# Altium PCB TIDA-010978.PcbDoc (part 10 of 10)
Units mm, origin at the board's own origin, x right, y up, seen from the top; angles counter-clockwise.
Board outline 243.95 x 94.85 mm, 4 copper layers (Top Layer, Mid Layer 1, Mid Layer 2, Bottom Layer), stack 1.623 mm thick; 865 components, 374 nets, 2308 pads, 2132 vias.
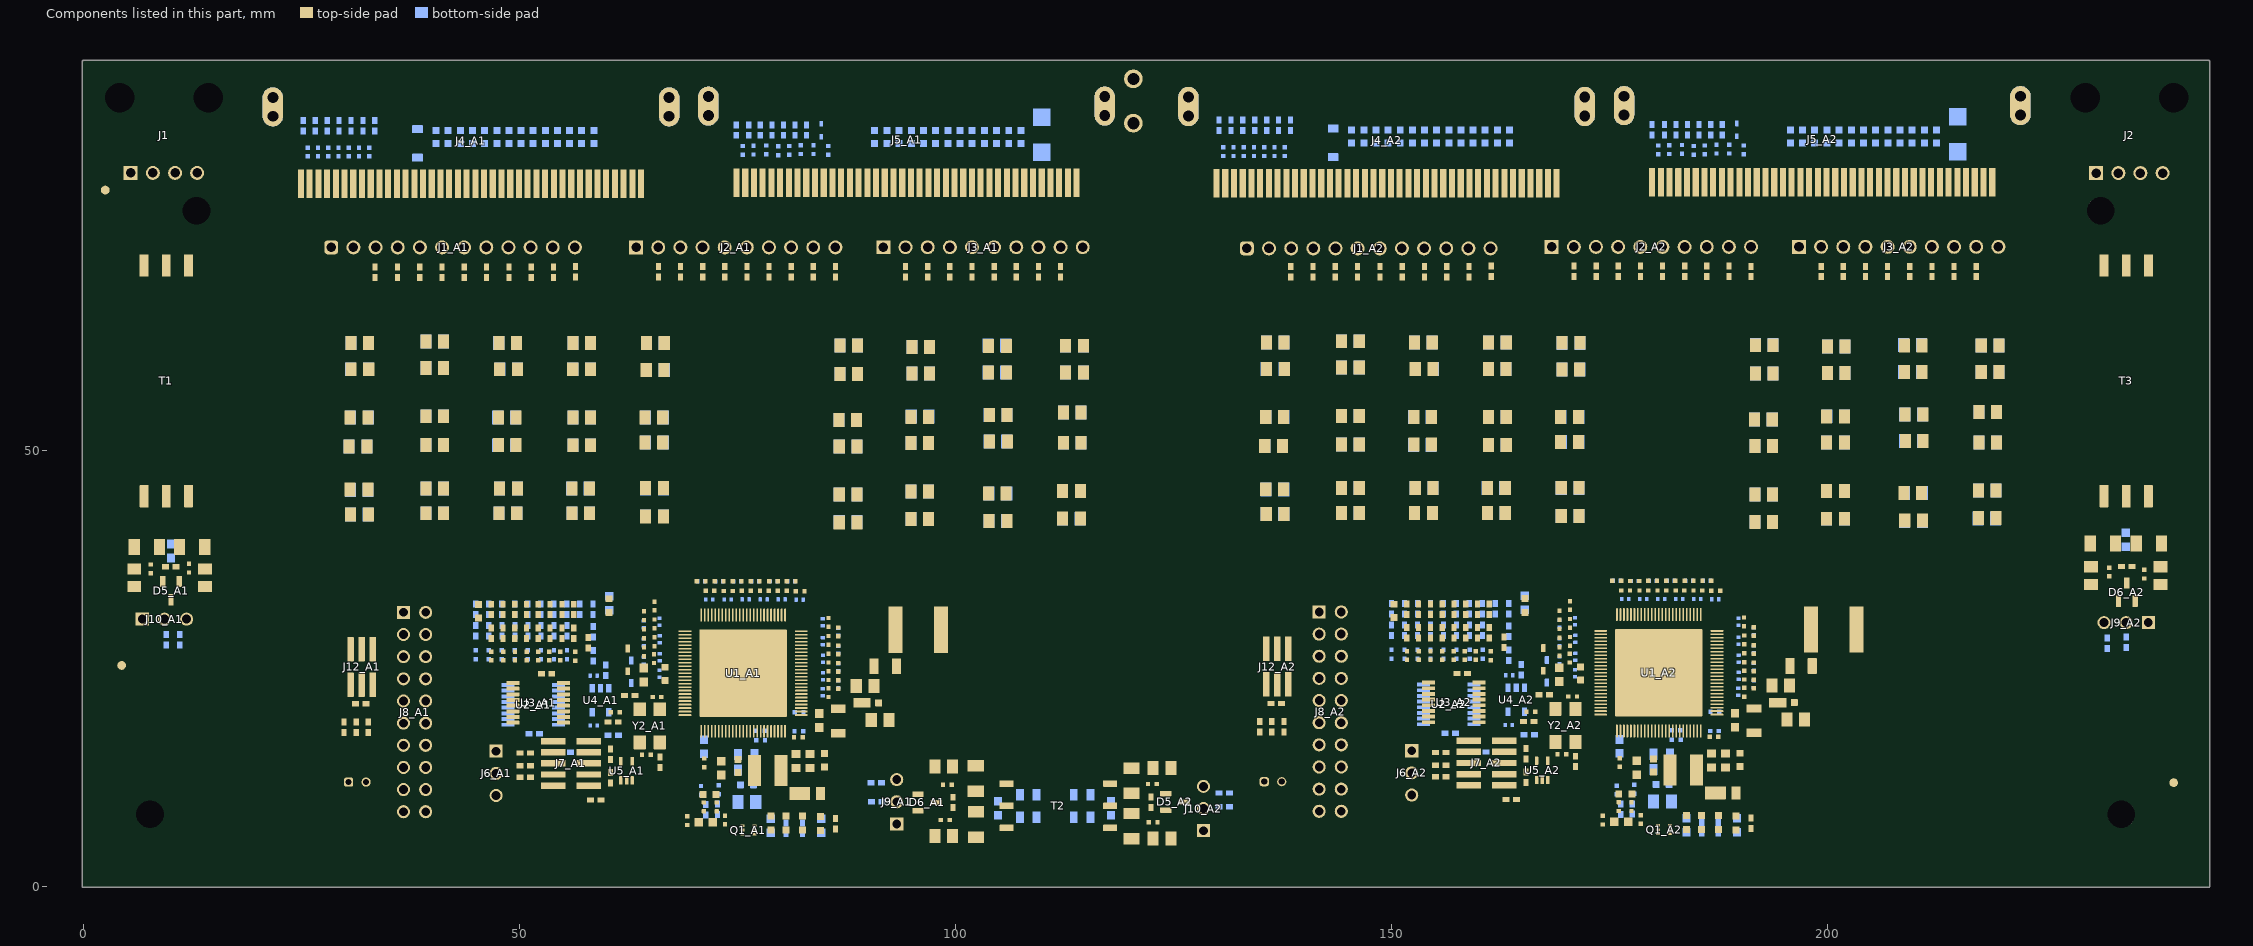
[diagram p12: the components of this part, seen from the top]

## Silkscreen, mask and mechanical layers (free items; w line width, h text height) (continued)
M9 Title Sheet:
  drawing of 56 lines, arcs and shapes, not listed
  text "1" at 26.882,339.887 h1.78
  text "2" at 111.354,339.887 h1.78
  text "3" at 195.936,339.887 h1.78
  text "4" at 280.645,339.887 h1.78
  text "5" at 365.1,339.887 h1.78
  text "6" at 449.809,339.887 h1.78
  text "A" at -11.76,294.726 h1.78
  text "A" at 488.62,294.726 h1.78
  text "B" at -11.76,199.476 h1.78
  text "B" at 488.62,199.476 h1.78
  text "C" at -11.76,104.226 h1.78
  text "C" at 488.62,104.226 h1.78
  text "D" at -11.76,8.976 h1.78
  text "D" at 488.62,8.976 h1.78
  text "PROJECT TITLE:" at 410.032,6.817 h1.14
  text ".PRJ_Title" at 411.302,3.431 h1.78
  text "DESIGNED FOR:" at 410.032,-0.828 h1.14
  text ".PRJ_Customer" at 411.302,-4.384 h1.78
  text "FILE NAME:" at 410.032,-8.448 h1.14
  text ".PCB_File_Name_No_Path" at 411.302,-11.496 h1.78
  text "Texas Instruments (TI) and/or its licensors do not warrant the accuracy or completeness of this specification" at 283.807,-15.607 h1.14
  text "ENGINEER:" at 410.032,-15.814 h1.14
  text "LAYOUT BY:" at 448.259,-15.814 h1.14
  text "or any information contained therein. TI and/or its licensors do not warrant that this design will meet" at 282.664,-18.469 h1.14
  text ".PRJ_Engineer" at 411.302,-19.751 h1.78
  text ".PCB_Layout" at 449.542,-19.751 h1.78
  text "the specifications, will be suitable for your application or fit for any particular purpose, or will operate in" at 282.664,-21.33 h1.14
  text ".Layer_Name" at 14.656,-21.806 h1.52
  text "ALTIUM DESIGNER VERSION:" at 448.259,-23.688 h1.14
  text "an implementation. TI and/or its licensors do not warrant that the design is production worthy. You should" at 282.664,-24.192 h1.14
  text "completely validate and test your design implementation to confirm the system functionality for your application." at 283.807,-27.054 h1.14
  text ".print_Scale" at 411.302,-27.075 h1.78
  text ".Application_BuildNumber" at 449.542,-27.075 h1.78
  text "1" at 26.882,-33.493 h1.78
  text "2" at 111.354,-33.493 h1.78
  text "3" at 195.936,-33.493 h1.78
  text "4" at 280.645,-33.493 h1.78
  text "5" at 365.1,-33.493 h1.78
  text "6" at 449.809,-33.493 h1.78
M10 Fab Notes:
  drawing of 189 lines, arcs and shapes, not listed
  text "DESIGN INFORMATION" at 436.322,161.675 h1.52
  text "MIN. TRACK WIDTH:" at 419.95,158.319 h1.52
  text "8" at 447.794,158.32 h1.52
  text "MIL" at 451.725,158.319 h1.52
  text "MIN. CLEARANCE:" at 419.95,155.167 h1.52
  text "MIL" at 451.725,155.167 h1.52
  text "7.874" at 443.475,155.05 h1.52
  text "MIN. VIA PAD SIZE:" at 419.95,152.014 h1.52
  text "24" at 447.033,152.014 h1.52
  text "MIL" at 451.725,152.014 h1.52
  text "0.05mm (2MIL)" at 437.603,148.714 h1.52
  text "MINIMUM ANNULAR RING" at 411.587,148.506 h1.52
  text "EXTERNAL" at 455.586,148.506 h1.52
  text "PER" at 416.667,145.708 h1.52
  text "IPC-D-275 CLASS 2 LEVEL C" at 422.255,145.708 h1.52
  text "MIL, HOLES" at 460.056,143.156 h1.52
  text "+/-" at 450.088,142.938 h1.52
  text "+/-" at 471.78,142.938 h1.52
  text "REGISTRATION TOLERANCES:" at 411.587,142.911 h1.52
  text "METAL" at 442.062,142.911 h1.52
  text "5" at 456.697,142.911 h1.52
  text "3" at 477.855,142.911 h1.52
  text "MIL" at 480.808,142.911 h1.52
  text "HOLE SIZE TOLERANCE (UNLESS OTHERWISE SPECIFIED):" at 411.587,140.414 h1.52
  text "+/-" at 471.78,140.341 h1.52
  text "3" at 477.855,140.314 h1.52
  text "MIL" at 480.808,140.314 h1.52
  text "MATERIAL:" at 409.688,136.818 h1.52
  text "FR-4 High Tg" at 434.744,133.553 h1.52
  text "X" at 431.075,133.35 h1.52
  text "FR-4" at 420.382,133.235 h1.52
  text "OTHER" at 458.177,133.235 h1.52
  text "62 MIL (1.6mm) +/-10%" at 428.512,129.602 h1.52
  text "X" at 425.462,129.54 h1.52
  text "THICKNESS:" at 411.587,129.394 h1.52
  text "OTHER" at 461.149,129.394 h1.52
  text "TOLERANCE:" at 411.587,125.88 h1.52
  text "X" at 433.133,125.88 h1.52
  text "ANSI IPC-6012 TYPE 3 CLASS 2" at 437.654,125.88 h1.52
  text "OTHER +/-" at 437.654,122.218 h1.52
  text "BOW & TWIST:" at 411.587,118.53 h1.52
  text "X" at 433.133,118.53 h1.52
  text "ANSI IPC-6012 TYPE 3 CLASS 2" at 437.654,118.53 h1.52
  text "OTHER +/-" at 437.654,114.804 h1.52
  text "DRILLING:" at 409.688,111.486 h1.52
  text "NC_DRILL FILES" at 454.418,108.815 h1.52
  text "REFERENCE:" at 411.587,108.715 h1.52
  text "X" at 428.281,108.712 h1.52
  text "AS SHOWN" at 432.802,108.715 h1.52
  text "X" at 451.167,108.715 h1.52
  text "OTHER" at 461.987,105.101 h1.52
  text "PTH COPPER THICKNESS:" at 411.579,105.012 h1.52
  text "X" at 440.516,105.012 h1.52
  text "20-30 um" at 443.767,105.012 h1.52
  text "BOARD FINISH:" at 409.688,101.263 h1.52
  text "SILKSCREEN:" at 413.631,98.466 h1.52
  text "X" at 437.959,98.466 h1.52
  text "TOP" at 440.93,98.466 h1.52
  text "X" at 450.913,98.466 h1.52
  text "BOTTOM" at 453.91,98.466 h1.52
  text "SILKSCREEN COLOR:" at 413.631,94.524 h1.52
  text "X" at 437.933,94.524 h1.52
  text "WHITE" at 440.93,94.524 h1.52
  text "OTHER" at 453.91,94.524 h1.52
  text "X" at 441.261,90.88 h1.52
  text "GREEN" at 444.258,90.88 h1.52
  text "OTHER" at 459.955,90.88 h1.52
  text "SOLDER RESIST COLOR:" at 413.631,90.706 h1.52
  text "X" at 441.261,86.962 h1.52
  text "MATTE" at 444.258,86.962 h1.52
  text "SEMI-GLOSS" at 459.943,86.946 h1.52
  text "IMMERSION GOLD (ENIG)" at 436.638,82.574 h1.52
  text "ENEPIG" at 470.611,82.39 h1.52
  text "SURFACE FINISH:" at 409.688,82.365 h1.52
  text "X" at 432.117,82.365 h1.52
  text "IMM. TIN/SILVER OR EQUIV" at 418.059,78.877 h1.52
  text "OTHER" at 454.418,78.777 h1.52
  text "ARRAY/PANEL:" at 409.688,74.831 h1.52
  text "CUT AND TRIM PER M1 BOARD OUTLINE" at 436.638,74.622 h1.52
  text "N.C. ROUTE" at 436.638,71.168 h1.52
  text "X" at 454.113,71.168 h1.52
  text "V. SCORE" at 458.634,71.168 h1.52
  text "CERTIFICATION:" at 409.688,67.888 h1.52
  text "MATERIALS AND WORKMANSHIP FOR ALL PCBS" at 428.103,67.888 h1.52
  text "TO MEET OR EXCEED THE REQUIREMENTS OF:" at 428.103,65.499 h1.52
  text "X" at 418.896,62.232 h1.52
  text "ANSI IPC-A-600F CLASS ->" at 422.147,62.232 h1.52
  text "X" at 464.006,62.232 h1.52
  text "2" at 466.8,62.232 h1.52
  text "1" at 458.799,62.194 h1.52
  text "3" at 475.792,62.194 h1.52
  text "X" at 439.521,58.481 h1.52
  text "RoHS" at 442.772,58.481 h1.52
  text "OTHER" at 459.14,58.481 h1.52
  text "PER ORDER" at 469.225,58.481 h1.52
  text "ALL BOARDS MUST MEET OR EXCEED UL94-V0 REQUIREMENTS." at 410.388,54.574 h1.52
  text "PCB MUST BEAR THE UL94V-0 UL REGISTERED MATERIAL ID NUMBER" at 410.388,51.626 h1.52
  text "ADDITIONAL REQUIREMENTS:" at 409.688,47.322 h1.52
  text "MICROSECTION:" at 411.587,44.601 h1.52
  text "YES" at 434.593,44.601 h1.52
  text "REQUIRED" at 456.475,40.935 h1.52
  text "BARE BOARD ELEC. TEST:" at 411.587,40.863 h1.52
  text "NONE" at 444.753,40.863 h1.52
  text "X" at 453.478,40.863 h1.52
  text "PER ORDER" at 471.512,40.863 h1.52
  text "XX MIL VIAS REQUIRE NON-CONDUCTIVE FILL AND PLANARIZE" at 415.858,35.657 h1.5
  text "XX MIL VIAS REQUIRE CONDUCTIVE FILL AND PLANARIZE" at 416.062,33.016 h1.52
  text "OUTER XX MIL TRACES REQUIRE 50 OHM SINGLE-ENDED IMPEDANCE" at 416.037,28.866 h1.47
  text "LAYER 2 & 3 (INNER LAYERS) XX MIL WIDE, XX MIL SPACE / TRACES REQUIRE 100 OHM DIFFERENTIAL IMPEDANCE" at 415.833,22.879 h1.52
  text ".Layer_Name" at 14.656,-21.806 h1.52
M11 Gerber Information:
  lines w0.254: -7.417,-23.626 160.223,-23.626 ; -7.417,-18.462 160.274,-18.462 ; -7.417,-13.297 -7.417,-28.791 94.31,-28.791 160.274,-28.791 160.274,-13.297 -7.404,-13.297 -7.404,-28.791 32.614,-28.791 ; 55.194,-28.791 55.194,-13.297 ; 87.376,-18.462 87.376,-13.297 ; 108.712,-18.462 108.712,-13.297 ; 124.511,-28.956 124.511,-23.804
  text "ALL ARTWORK VIEWED FROM TOP SIDE" at -5.804,-16.654 h1.52
  text "BOARD #:" at 57.099,-16.654 h1.52
  text ".PRJ_Number" at 70.955,-16.654 h1.52
  text "REV:" at 92.405,-16.654 h1.52
  text ".PCB_Rev" at 99.809,-16.654 h1.52
  text "SVN REV:" at 113.69,-16.654 h1.52
  text ".VersionControl_RevNumber" at 126.543,-16.654 h1.52
  text "LAYER NAME =" at -5.804,-21.806 h1.52
  text "PLOT NAME =" at -5.804,-27.034 h1.52
  text ".plot_File_Name" at 14.656,-27.034 h1.52
  text "GENERATED    :" at 57.15,-27.034 h1.52
  text ".Print_Date" at 79.235,-27.034 h1.52
  text ".Print_Time" at 97.752,-27.034 h1.52
  text "TEXAS INSTRUMENTS" at 129.87,-27.034 h1.52
M12 Stackup:
  drawing of 295 lines, arcs and shapes, not listed
  text "Layer" at 370.969,332.524 h1.52
  text "Name" at 381.38,332.524 h1.52
  text "Material" at 404.996,332.524 h1.52
  text "Thickness" at 426.834,332.524 h1.52
  text "Constant" at 443.34,332.524 h1.52
  text "Board Layer Stack" at 457.814,332.524 h1.52
  text "Top Overlay" at 381.38,329.476 h1.52
  text "Top Solder" at 381.38,326.428 h1.52
  text "Solder Resist" at 404.996,326.428 h1.52
  text "0.40mil" at 426.834,326.428 h1.52
  text "3.5" at 443.34,326.428 h1.52
  text "1" at 370.969,323.38 h1.52
  text "Top Layer" at 381.38,323.38 h1.52
  text "2.76mil" at 426.834,323.38 h1.52
  text "Dielectric 1" at 381.38,320.332 h1.52
  text "PP-006" at 404.996,320.332 h1.52
  text "8.00mil" at 426.834,320.332 h1.52
  text "4.1" at 443.34,320.332 h1.52
  text "2" at 370.969,317.284 h1.52
  text "Mid Layer 1" at 381.38,317.284 h1.52
  text "CF-004" at 404.996,317.284 h1.52
  text "1.40mil" at 426.834,317.284 h1.52
  text "Dielectric1" at 381.38,314.236 h1.52
  text "FR-4 High Tg" at 404.996,314.236 h1.52
  text "39.60mil" at 426.834,314.236 h1.52
  text "4.8" at 443.34,314.236 h1.52
  text "3" at 370.969,311.188 h1.52
  text "Mid Layer 2" at 381.38,311.188 h1.52
  text "CF-004" at 404.996,311.188 h1.52
  text "1.40mil" at 426.834,311.188 h1.52
  text "Dielectric 2" at 381.38,308.14 h1.52
  text "PP-006" at 404.996,308.14 h1.52
  text "8.00mil" at 426.834,308.14 h1.52
  text "4.1" at 443.34,308.14 h1.52
  text "4" at 370.969,305.092 h1.52
  text "Bottom Layer" at 381.38,305.092 h1.52
  text "2.76mil" at 426.834,305.092 h1.52
  text "Bottom Solder" at 381.38,302.044 h1.52
  text "Solder Resist" at 404.996,302.044 h1.52
  text "0.40mil" at 426.834,302.044 h1.52
  text "3.5" at 443.34,302.044 h1.52
  text "Bottom Overlay" at 381.38,298.996 h1.52
  text ".Layer_Name" at 14.656,-21.806 h1.52
M13 Component Bodies Top:
  text ".Layer_Name" at 14.656,-21.806 h1.52
M14 Component Bodies Bottom:
  text ".Layer_Name" at 14.656,-21.806 h1.52
M15 Courtyards Top:
  text ".Layer_Name" at 14.656,-21.806 h1.52
M16 Courtyards Bottom:
  text ".Layer_Name" at 14.656,-21.806 h1.52
Drill Drawing:
  circle w0.254: c176.279,218.649 r0.42
  circle w0.254: c176.279,218.649 r0.7
  circle w0.254: c176.279,206.047 r0.7
  lines w0.254: 175.579,187.846 176.979,187.846 176.279,186.446 175.579,187.846 ; 175.579,190.996 176.979,190.996 176.279,189.596 175.579,190.996 ; 175.579,193.096 175.929,193.096 176.279,192.746 176.629,193.096 176.979,193.096 176.629,193.446 176.979,193.796 176.629,193.796 176.279,194.146 175.929,193.796 175.579,193.796 175.929,193.446 175.579,193.096 ; 175.579,195.897 175.579,196.247 175.929,196.597 175.579,196.947 175.579,197.297 175.929,197.297 176.279,196.947 176.629,197.297 176.979,197.297 176.979,196.947 176.629,196.597 176.979,196.247 176.979,195.897 176.629,195.897 176.279,196.247 175.929,195.897 175.579,195.897 ; 175.579,199.047 176.979,199.047 176.979,200.447 175.579,200.447 175.579,199.047 ; 175.579,202.197 176.279,202.547 176.979,202.197 176.629,202.897 176.979,203.597 176.279,203.247 175.579,203.597 175.929,202.897 175.579,202.197 ; 175.579,208.498 176.979,208.498 176.979,209.898 175.579,209.898 175.579,208.498 ; 175.579,212.348 176.279,211.648 176.979,212.348 176.279,213.048 175.579,212.348 ; 175.579,215.148 175.929,215.148 175.929,214.798 176.629,214.798 176.629,215.148 176.979,215.148 176.979,215.848 176.629,215.848 176.629,216.198 175.929,216.198 175.929,215.848 175.579,215.848 175.579,215.148 ; 175.859,187.566 176.699,187.566 176.279,186.726 175.859,187.566 ; 175.859,208.778 176.699,208.778 176.699,209.618 175.859,209.618 175.859,208.778
  lines w0.305: 174.309,185.501 256.312,185.501 ; 174.309,220.154 256.312,220.154 ; 182.884,182.35 182.884,223.304 ; 191.313,182.35 191.313,223.304 ; 207.477,182.35 207.477,223.304 ; 214.055,182.35 214.055,223.304 ; 223.579,182.35 223.579,223.304 ; 241.932,182.35 241.932,223.304 ; 174.309,182.35 256.312,182.35 256.312,223.304 174.309,223.304 174.309,182.35
  text "Symbol" at 176.2,221.099 h1.83
  text "Quantity" at 183.83,221.099 h1.83
  text "Finished Hole Size" at 192.258,221.099 h1.83
  text "Plated" at 208.422,221.099 h1.83
  text "Hole Type" at 215,221.099 h1.83
  text "Drill Layer Pair" at 224.524,221.099 h1.83
  text "Hole Tolerance" at 242.877,221.099 h1.83
  text "4" at 183.83,217.948 h1.52
  text "125.00mil (3.175mm)" at 192.258,217.948 h1.52
  text "NPTH" at 208.422,217.948 h1.52
  text "Round" at 215,217.948 h1.52
  text "Top Layer - Bottom Layer" at 224.524,217.948 h1.52
  text "4" at 183.83,214.798 h1.52
  text "133.86mil (3.400mm)" at 192.258,214.798 h1.52
  text "NPTH" at 208.422,214.798 h1.52
  text "Round" at 215,214.798 h1.52
  text "Top Layer - Bottom Layer" at 224.524,214.798 h1.52
  text "397" at 183.83,211.648 h1.52
  text "7.87mil (0.200mm)" at 192.258,211.648 h1.52
  text "PTH" at 208.422,211.648 h1.52
  text "Round" at 215,211.648 h1.52
  text "Top Layer - Bottom Layer" at 224.524,211.648 h1.52
  text "1735" at 183.83,208.498 h1.52
  text "12.01mil (0.305mm)" at 192.258,208.498 h1.52
  text "PTH" at 208.422,208.498 h1.52
  text "Round" at 215,208.498 h1.52
  text "Top Layer - Bottom Layer" at 224.524,208.498 h1.52
  text "4" at 183.83,205.347 h1.52
  text "27.56mil (0.700mm)" at 192.258,205.347 h1.52
  text "PTH" at 208.422,205.347 h1.52
  text "Round" at 215,205.347 h1.52
  text "Top Layer - Bottom Layer" at 224.524,205.347 h1.52
  text "+3.94mil/-0.00mil" at 242.877,205.347 h1.52
  text "40" at 183.83,202.197 h1.52
  text "39.37mil (1.000mm)" at 192.258,202.197 h1.52
  text "PTH" at 208.422,202.197 h1.52
  text "Round" at 215,202.197 h1.52
  text "Top Layer - Bottom Layer" at 224.524,202.197 h1.52
  text "18" at 183.83,199.047 h1.52
  text "40.00mil (1.016mm)" at 192.258,199.047 h1.52
  text "PTH" at 208.422,199.047 h1.52
  text "Round" at 215,199.047 h1.52
  text "Top Layer - Bottom Layer" at 224.524,199.047 h1.52
  text "8" at 183.83,195.897 h1.52
  text "42.91mil (1.090mm)" at 192.258,195.897 h1.52
  text "PTH" at 208.422,195.897 h1.52
  text "Round" at 215,195.897 h1.52
  text "Top Layer - Bottom Layer" at 224.524,195.897 h1.52
  text "64" at 183.83,192.746 h1.52
  text "43.31mil (1.100mm)" at 192.258,192.746 h1.52
  text "PTH" at 208.422,192.746 h1.52
  text "Round" at 215,192.746 h1.52
  text "Top Layer - Bottom Layer" at 224.524,192.746 h1.52
  text "16" at 183.83,189.596 h1.52
  text "49.21mil (1.250mm)" at 192.258,189.596 h1.52
  text "PTH" at 208.422,189.596 h1.52
  text "Round" at 215,189.596 h1.52
  text "Top Layer - Bottom Layer" at 224.524,189.596 h1.52
  text "2" at 183.83,186.446 h1.52
  text "55.12mil (1.400mm)" at 192.258,186.446 h1.52
  text "PTH" at 208.422,186.446 h1.52
  text "Round" at 215,186.446 h1.52
  text "Top Layer - Bottom Layer" at 224.524,186.446 h1.52
  text "2292 Total" at 183.83,183.295 h1.52
  text ".Layer_Name" at 14.656,-21.806 h1.52
M17 Embedded Cavity:
  text ".Layer_Name" at 14.656,-21.806 h1.52
M18 Embedded Assembly:
  text ".Layer_Name" at 14.656,-21.806 h1.52
M19 Embedded Keepout:
  text ".Layer_Name" at 14.402,-21.806 h1.52

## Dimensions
-0.2,95.125 to 243.95,94.6 on M2 Board Dimensions
243.875,-0.025 to 243.95,94.6 on M2 Board Dimensions
0,-10.16 to 25.4,-10.16 on M2 Board Dimensions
